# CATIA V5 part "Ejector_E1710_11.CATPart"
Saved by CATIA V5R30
Part number: Vyhazovac_2.5x160_9
Nomenclature: E1710/2.5x160
Description: MEUSBURGER
Property "Material": "1.221"
Publications: "__DrillHole", "Base"
Bounding box of the stored display mesh (mm): x -2.499 to 2.499, y -2.499 to 2.499, z 0 to 152
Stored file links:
  E:\Bakalarka\Model\Forma_v7\Ejector_E1710_11.CATPart
  E:\dev\MoldDesign\intel_a\startup\components\MoldCatalog\Ejector\Meusburger\Ejector_E1710\TableE1710.txt
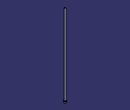
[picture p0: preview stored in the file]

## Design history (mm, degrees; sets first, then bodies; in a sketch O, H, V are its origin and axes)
Parameters
  Ref = "E1710/2.5x160" {design table}
  D1 = 2.5 mm {design table}
  D3 = 5 mm {design table}
  L = 160 mm {design table}
  L3 = 2 mm {design table}
  R = 0.3 mm {design table}
  k_d3 = 6 mm {design table}
  k_d1 = 2.7 mm {design table}
  k_F = 0.3 mm {design table}
  kl = 17 mm {design table}
  Mat = "1.221" {design table}
  HeatTreat = "ISO6751" {design table}
  Offset_Parting = 10 mm
  Anti_Rotation = "Normal"
  Anti_Rotation_D = 1.55 mm
  Anti_Rotation_D_Icut = 1.55 mm
  Add_Length_L = 0.0877 mm
  Add_Length_D3 = 0 mm
  SupplierRef = "Meusburger 2017"
  BmpRef = "F_MldEjectorD1"
  DrillHole_Length = 225 mm
  ValidationTest = false
  Anti_Rotation_D_min = 1.55 mm {= OffSet_D1 /2}
  Anti_Rotation_D_max = 2.425 mm {= D3/2-0.075mm}
  Anti_Rotation_D_ref = 1.55 mm {= Anti_Rotation_D}
  Anti_Rotation_D_Icut_ref = 1.55 mm {= Anti_Rotation_D_Icut}
  Anti_Rotation_Ref_Icut = 2.3246 mm
  Offset_L = 20 mm
  D = 2.5 mm {= D1}
  OffSet_D1 = 3.1 mm {= D1+2*R}
  OffSet_D3 = 6 mm {= D3+1mm}
  XG_Split = 58 mm
  YG_Split = 61 mm
  ZG_Split = -198 mm
  DirX_Split = 0 mm
  DirY_Split = 0 mm
  DirZ_Split = 1 mm
Set1 "BaseBody"
  Point1 "Base": (0, 0, 0)
  Plane1: type Offset, RefPlane xy-plane, Offset 225 {= DrillHole_Length}, reversed
  Sketch1 "Sketch.2" on xy-plane, origin (0, 0, 0), H (1, 0, 0), V (0, 1, 0)
    point P1 (-0.46, 1.1623)
    point P2 (0.46, 1.1623)
    construction line L1 (-0.46, 1.1623) -> (0.46, 1.1623)
    point P3 (0.46, -1.1623)
    line L2 (0.46, -1.1623) -> (0.46, 1.1623)
    point P4 (-0.46, -1.1623)
    construction line L3 (0.46, -1.1623) -> (-0.46, -1.1623)
    line L4 (-0.46, 1.1623) -> (-0.46, -1.1623)
    point P5 (-0.21, 1.1623)
    arc A1 centre (-0.21, 1.1623) radius 0.25 from (-0.21, 1.4123) to (-0.46, 1.1623) ccw
    point P7 (0.21, 1.1623)
    point P8 (0.21, 1.4123)
    arc A2 centre (0.21, 1.1623) radius 0.25 from (0.46, 1.1623) to (0.21, 1.4123) ccw
    line L5 (-0.21, 1.4123) -> (0.21, 1.4123)
    point P9 (-0.46, -1.1623)
    arc A3 centre (-0.21, -1.1623) radius 0.25 from (-0.46, -1.1623) to (-0.21, -1.4123) ccw
    point P11 (0.21, -1.4123)
    line L6 (-0.21, -1.4123) -> (0.21, -1.4123)
    point P12 (0.46, -1.1623)
    arc A4 centre (0.21, -1.1623) radius 0.25 from (0.21, -1.4123) to (0.46, -1.1623) ccw
    point P14 (-0.46, 1.1623)
    point P15 (-0.46, -1.1623)
    point P16 (0.46, 1.1623)
    point P17 (0.46, -1.1623)
    reference projected circle E1 centre (0, 0) radius 1.25 from edge [face of Shaft1 from Sketch2.L3 | face of Shaft1 from Sketch2.L4]
    reference projected circle E2 centre (0, 0) radius 1.25 from edge [face of Shaft1 from Sketch2.L3 | face of Shaft1 from Sketch2.L4]
    reference projected circle E3 centre (0, 0) radius 1.25 from edge [face of Shaft1 from Sketch2.L3 | face of Shaft1 from Sketch2.L4]
    reference projected circle E4 centre (0, 0) radius 1.25 from edge [face of Shaft1 from Sketch2.L3 | face of Shaft1 from Sketch2.L4]
    point P18 (-0.46, -1.1623)
    point P19 (-0.21, -1.4123)
    point P20 (0.21, -1.4123)
    point P21 (0.46, -1.1623)
    point P22 (-0.21, -1.4123)
    point P23 (0.21, -1.4123)
    distance P14 P15 = 2.3246 (reference)
    distance P16 P17 = 2.3246 (reference)
    distance L1 P14 = 0 (reference)
    radius A1 = 1.25
    distance L4 V = 1.56
    distance L2 V = 2.435
    distance L5 L6 = 5
    horizontal: L1 H, L3 H, L5 H
    vertical: L2 V, L4 V
    coincidence: P5 L1, P7 L1, P3 P12, P14 L4, P15 L4, P16 L2, P17 L2, P14 E1, P15 E2, P16 E3, P17 E4, P3 P21, P4 P18, P20 P23, P19 P22
    tangency: A1 L4, A2 L2, A2 L5, A1 L5
    symmetry: P1 P9 H, A1 A3 H, P8 P11 H, L5 L6 H, P2 P12 H, A2 A4 H
  DatumSurface1
Body1 "PartBody" (main body)
  Sketch2 "Sketch.1" on zx-plane, origin (0, 0, 0), H (-1, 0, 0), V (0, 0, 1)
    point P1 (0, 160)
    line L1 (1.25, 160) -> (0, 160)
    line L2 (1.25, 2) -> (1.25, 160)
    line L3 (2.5, 2) -> (1.25, 2)
    line L4 (2.5, 0) -> (2.5, 2)
    point P5 (0, 0)
    line L5 (0, 0) -> (2.5, 0)
    point P6 (0, 160)
    axis line L6 (0, 160) -> (0, 0)
    point P7 (0, 0)
    point P8 (1.25, 2)
    point P9 (1.25, 2)
    line L7 (0, 160) -> (0, 0)
    distance L5 L3 = 2 {= L3}
    distance L5 L1 = 160 {= L}
    distance L2 L6 = 1.25 {= D1 /2}
    distance L4 L6 = 2.5 {= D3 /2}
    coincidence: L6 P5, P1 L6, L5 H, L6 V, P7 O, P6 P1, P8 P9
    vertical: L2 V, L7 V
    horizontal: L1 H
  Shaft1 "Shaft.1": profile Sketch2, axis Sketch2.L6, angle 360
  Pocket1 "Pocket.1": profile Sketch1, direction (0, 0, 1), length 3, outer side, deactivated
  Pocket2 "Pocket.2": profile Sketch1, direction (0, 0, 1), length 3, outer side, deactivated
  Fillet1: radius 0.3 {= R}, on edge [face of Shaft1 from Sketch2.L2 | face of Shaft1 from Sketch2.L3]
  Pocket3: profile face of Shaft1 from Sketch2.L1, direction along face of Shaft1 from Sketch2.L1 reversed, up to face of DatumSurface1
Body2 "__DrillHole"
  Sketch3 "Sketch.3" on face of Shaft1, origin (0, 0, 0), H (1, 0, 0), V (0, -1, 0)
    point P1 (0, 0)
    reference projected point E1 (0, 0) from Point1
    coincidence: E1 P1
  Hole1 "Hole.1": placed by Sketch3, at (0, 0, 0) direction (0, 0, 1), diameter 3.1 {= OffSet_D1}, depth 140 {= L-Offset_L}
  Sketch4 "Sketch.4" on face of Shaft1, origin (0, 0, 0), H (1, 0, 0), V (0, -1, 0)
    point P1 (0, 0)
    reference projected point E1 (0, 0) from Point1
    coincidence: E1 P1
  Hole2 "Hole.2": placed by Sketch4, at (0, 0, 0) direction (0, 0, 1), diameter 2.5 {= D1}, depth 160 {= L}
  Sketch5 "Sketch.5" on face of Shaft1 from Sketch2.L3, origin (0, 0, 2), H (1, 0, 0), V (0, 1, 0)
    point P1 (0, 0)
    reference projected point E1 (0, 0) from Point1
    coincidence: E1 P1
  Hole3 "Hole.3": placed by Sketch5, at (0, 0, 2) direction (0, 0, -1), diameter 6 {= OffSet_D3}, depth 227 {= L3 +DrillHole_Length}
  Chamfer1: length 0.3 {= k_F}, angle 45, on edge [face of Hole1 | face of Hole3]
  Body3 "__Body.1"
    Pocket4 "Pocket.3": profile Sketch1, direction (0, 0, -1), length 225, opposite side length 2, deactivated
  Assemble1: tool Body3
  Chamfer2: length 0.3 {= k_F}, angle 45, on edge [start face of Pocket4 | face of Hole1], deactivated
  Body4 "__Body.2"
    Pocket5 "Pocket.4": profile Sketch1, direction (0, 0, -1), length 225, opposite side length 2, deactivated
  Assemble2: tool Body4
  Chamfer3: length 0.3 {= k_F}, angle 45, on edge [start face of Pocket5 | face of Hole1], deactivated
Relations
  design table "TableE1710", configuration 134, drives Ref, D1, D3, L, L3, R, k_d3, k_d1, k_F, kl, Mat, HeatTreat
  Offset_L = 20mm (deactivated)
  rule "Cut_Head_rule":
    let sketch_cut (length)
    let PartBody_Pocket_Sketch (Boolean)
    let I_PartBody_Pocket (Boolean)
    let D_PartBody_Pocket (Boolean)
    let N_DrillHole_Hole (Boolean)
    let N_DrillHole_Hole_Sketch (Boolean)
    let I_DrillHole_Pocket (Boolean)
    let D_DrillHole_Pocket (Boolean)
    /* --------------------------------------------------------------------------------------*/
    if Anti_Rotation =="Normal"
    {
    	sketch_cut=Anti_Rotation_D_max
    	PartBody_Pocket_Sketch = false
    	I_PartBody_Pocket = false
    	D_PartBody_Pocket = false
    	N_DrillHole_Hole = true
    	N_DrillHole_Hole_Sketch = true
    	I_DrillHole_Pocket = false
    	D_DrillHole_Pocket = false
    	Chamfer1.Activity= true
    	Chamfer2.Activity= false
    	Chamfer3.Activity= false
    }
    if Anti_Rotation == "I_Cut"
    {
    	sketch_cut=Anti_Rotation_D_Icut_ref
    	PartBody_Pocket_Sketch = true
    	I_PartBody_Pocket = true
    	D_PartBody_Pocket = false
    	N_DrillHole_Hole = false
    	N_DrillHole_Hole_Sketch = false
    	I_DrillHole_Pocket = true
    	D_DrillHole_Pocket = false
    	Chamfer1.Activity= false
    	Chamfer2.Activity= true
    	Chamfer3.Activity= false
    }
    if Anti_Rotation =="D_Cut"
    {
    	sketch_cut=Anti_Rotation_D_max
    	PartBody_Pocket_Sketch = true
    	I_PartBody_Pocket = false
    	D_PartBody_Pocket = true
    	N_DrillHole_Hole = false
    	N_DrillHole_Hole_Sketch = false
    	I_DrillHole_Pocket = false
    	D_DrillHole_Pocket = true
    	Chamfer1.Activity= false
    	Chamfer2.Activity= false
    	Chamfer3.Activity= true
    }
    /* --------------------------------------------------------------------------------------*/
    Sketch1.distance(L2 V) = sketch_cut+0.01mm
    Sketch1.distance(L4 V) =Anti_Rotation_D_ref+0.01mm
    Sketch1.radius(A1) =D/2
    Pocket4.FirstLimit.Depth = DrillHole_Length
    Pocket5.FirstLimit.Depth = DrillHole_Length
    Pocket1.FirstLimit.Depth = L3+1mm
    Pocket2.FirstLimit.Depth = L3+1mm
    Pocket4.SecondLimit.Depth = L3
    Pocket5.SecondLimit.Depth =L3
    Pocket1.Activity = I_PartBody_Pocket
    Pocket2.Activity = D_PartBody_Pocket
    Sketch1.Activity =PartBody_Pocket_Sketch
    Hole3.Activity= N_DrillHole_Hole
    Sketch5.Activity = N_DrillHole_Hole_Sketch
    Pocket4.Activity = I_DrillHole_Pocket
    Pocket5.Activity  = D_DrillHole_Pocket
  rule "Anti_Rotation_Icut_constrain":
    let Ref1(length)
    let Ref2(length)
    let Ref3(length)
    let Diam1(length)
    let Diam2(length)
    let Add_Length_Lmin (length)
    Ref1=Sketch1.distance(P14 P15)
    Ref2=Sketch1.distance(P16 P17)
    Diam1=D
    Diam2=D3
    /* --------------------------------------------------------------------*/
    if Ref1 >Ref2
    	Anti_Rotation_Ref_Icut = Ref1
    else
    	Anti_Rotation_Ref_Icut  =Ref2
    Add_Length_D3 .InferiorRange=Anti_Rotation_Ref_Icut /2+Diam1/2 -Diam2/2
    if Add_Length_D3 .InferiorRange<0mm
    	Add_Length_D3 .InferiorRange=0mm
    if ValidationTest == "true"
    	Ref3   = 2*Add_Length_L +Anti_Rotation_Ref_Icut  +2*Diam1/2
    else
    	Ref3  =Diam2+2*Add_Length_D3
    if Ref3 <Diam2
    {
    	Ref3 =Diam2
    }
    /* --------------------------------------------------------------------*/
    Sketch1.distance(L5 L6) = Ref3
    Add_Length_L .InferiorRange=Diam2/2-Anti_Rotation_Ref_Icut/2-Diam1/2
    Add_Length_Lmin=Diam2/2-Anti_Rotation_Ref_Icut/2-Diam1/2
    if Add_Length_Lmin<0mm
    	Add_Length_L .InferiorRange=0mm
    else
    	Add_Length_L .InferiorRange=Add_Length_Lmin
